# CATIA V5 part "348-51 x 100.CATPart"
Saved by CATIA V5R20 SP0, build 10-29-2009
Part number: 348-51 x 100
Definition: NONE
Nomenclature: 348-51 x 100
Source: Unknown
Description: 348-51 x 100
Bounding box of the stored display mesh (mm): x 0 to 100, y -35 to 35, z -35 to 35
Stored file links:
  C:\Users\Utente\Desktop\IO LAVORO\3D X SITO CF\X SITO\3D files 348\348-51 x 100.CATPart
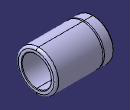
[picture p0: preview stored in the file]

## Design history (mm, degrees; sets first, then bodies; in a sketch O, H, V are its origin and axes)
Body1 "348-51 x 100" (main body)
  Solid1: solid without history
